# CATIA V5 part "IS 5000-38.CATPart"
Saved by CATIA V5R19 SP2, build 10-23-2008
Part number: IS 5000-38
Bounding box of the stored display mesh (mm): x -59.975 to 59.975, y -59.975 to 59.975, z 0 to 216
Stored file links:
  C:\Users\Bora\Desktop\3D Katı model\IS serisi\IS 5000\IS 5000-38.CATPart
  C:\Program Files\Dassault Systemes\B19\intel_a\reffiles\standard\MetricThickPitch.txt
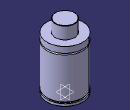
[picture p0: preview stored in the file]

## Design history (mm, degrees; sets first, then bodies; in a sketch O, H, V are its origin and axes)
Body1 (main body)
  Sketch1 on yz-plane, origin (0, 0, 0), H (0, 1, 0), V (0, 0, 1)
    point P1 (60, 155)
    point P2 (60, 150)
    point P5 (32.5, 215)
    point P7 (32.5, 215)
    point P12 (60, 150)
    point P13 (60, 155)
    arc A1 centre (60, 152.5) radius 2.5 from (60, 155) to (60, 150) ccw
    line L1 (60, 0) -> (60, 8)
    line L2 (32.5, 215) -> (32.5, 175)
    arc A2 centre (31.5, 215) radius 1 from (32.5, 215) to (31.5, 216) ccw
    line L3 (56, 13) -> (56, 8)
    line L4 (60, 13) -> (60, 150)
    line L5 (60, 155) -> (60, 175)
    line L6 (31.5, 216) -> (0, 216)
    point P15 (0, 216)
    line L7 (32.5, 175) -> (60, 175)
    line L8 (0, 0) -> (60, 0)
    line L9 (56, 13) -> (60, 13)
    line L10 (56, 8) -> (60, 8)
    coincidence: P15 V, P1 P13, P2 P12, P5 P7
    tangency: L6 A2
    horizontal: L7 H, L8 H, L9 H, L10 H
  Shaft1: profile Sketch1, axis Sketch1.V, angle 360
  Sketch2 on face of Shaft1 from Sketch1.L8, origin (0, 0, 0), H (1, 0, 0), V (0, -1, 0)
    point P1 (40, 0)
    distance P1 V = 40
  Hole1: placed by Sketch2, at (40, 0, 0) direction (0, 0, 1), diameter 8.376, depth 16, threaded "M10", thread diameter 10, thread depth 16, pitch 1.5
  CircPattern1: of Hole1, instances 4, angular step 90, axis from xy-plane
